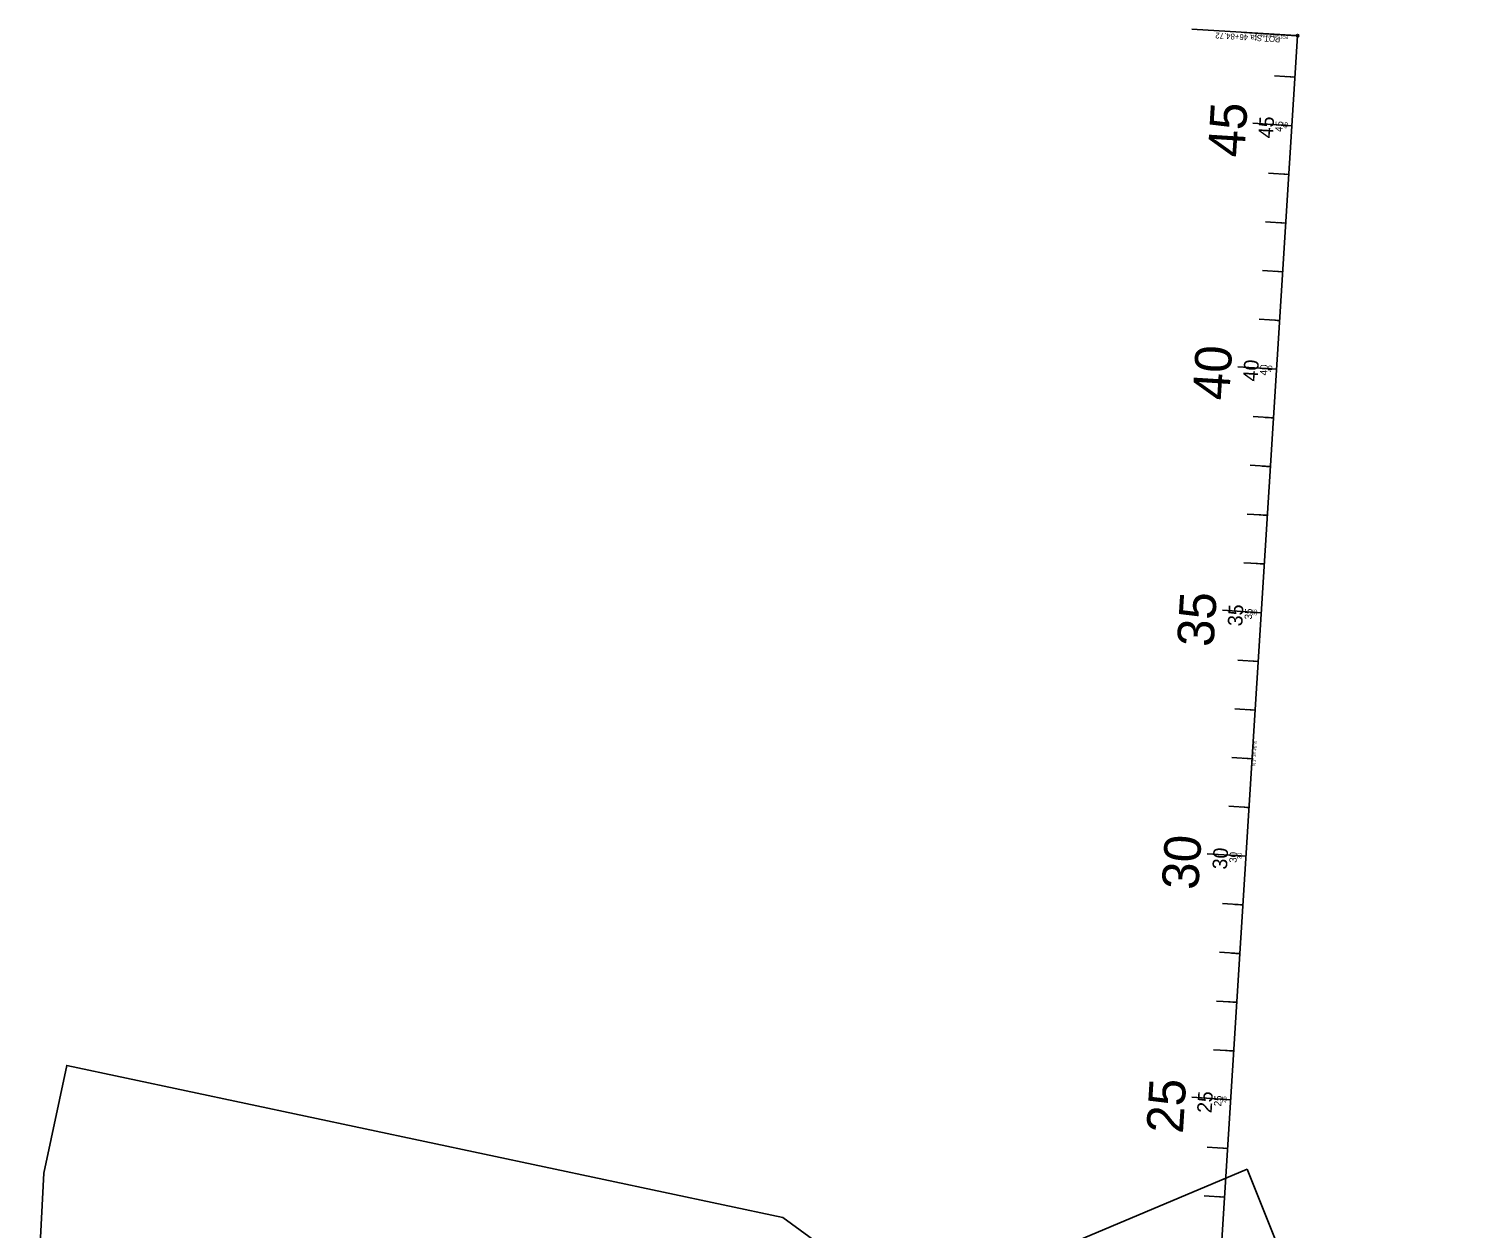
# Model space of a CAD drawing. Extents: x 2358865 to 2362945, y 393485 to 404880.
# Drawn here: x 2359965 to 2362945, y 402421 to 404880 of the extents above; entities that cross this region are included whole.
import ezdxf

# ---------------------------------------------------------------- set-up
doc = ezdxf.new("R2010")
doc.units = 0
for name, color, linetype in [('CL', 7, 'Continuous'), ('Level 21', 7, 'Continuous'), ('Level 25', 7, 'Continuous'), ('Level 28', 7, 'Continuous'), ('Level 30', 7, 'Continuous'), ('Level 33', 7, 'Continuous'), ('Level 39', 7, 'Continuous'), ('Level 41', 7, 'Continuous'), ('Level 63', 7, 'Continuous')]:
    doc.layers.add(name, color=color, linetype=linetype)

msp = doc.modelspace()

# ---------------------------------------------------------------- linework, layer by layer
at = {"layer": 'CL'}
msp.add_line((2362381, 401942.4), (2362564.8, 404866.6), dxfattribs=at)
at = {"layer": 'Level 25'}
for p, q in [((2362559.5, 404782), (2362554.5, 404782.3)), ((2362553.2, 404682.2), (2362545.2, 404682.7)), ((2362546.9, 404582.4), (2362541.9, 404582.7)), ((2362540.6, 404482.6), (2362535.7, 404482.9)), ((2362534.4, 404382.8), (2362529.4, 404383.1)), ((2362528.1, 404283), (2362523.1, 404283.3)), ((2362521.8, 404183.2), (2362513.8, 404183.7)), ((2362515.6, 404083.4), (2362510.6, 404083.7)), ((2362509.3, 403983.6), (2362504.3, 403983.9)), ((2362503, 403883.8), (2362498, 403884.1)), ((2362496.7, 403784), (2362491.8, 403784.3)), ((2362490.5, 403684.2), (2362482.5, 403684.7)), ((2362484.2, 403584.4), (2362479.2, 403584.7)), ((2362477.9, 403484.6), (2362472.9, 403484.9)), ((2362471.7, 403384.8), (2362466.7, 403385.1)), ((2362465.4, 403285), (2362460.4, 403285.3)), ((2362459.1, 403185.2), (2362451.1, 403185.7)), ((2362452.8, 403085.4), (2362447.8, 403085.7)), ((2362446.6, 402985.6), (2362441.6, 402985.9)), ((2362440.3, 402885.8), (2362435.3, 402886.1)), ((2362434, 402786), (2362429, 402786.3)), ((2362427.7, 402686.2), (2362419.8, 402686.7)), ((2362421.5, 402586.4), (2362416.5, 402586.7)), ((2362415.2, 402486.6), (2362410.2, 402486.9))]:
    msp.add_line(p, q, dxfattribs=at)
at = {"layer": 'Level 28'}
msp.add_line((2362563.5, 404866.7), (2362455.2, 404873.5), dxfattribs=at)
msp.add_circle((2362564.8, 404866.6), 1.25, dxfattribs=at)
at = {"layer": 'Level 30'}
for p, q in [((2362559.5, 404782), (2362551, 404782.6)), ((2362553.2, 404682.2), (2362537.2, 404683.2)), ((2362546.9, 404582.4), (2362538.4, 404583)), ((2362540.6, 404482.6), (2362532.2, 404483.2)), ((2362534.4, 404382.8), (2362525.9, 404383.4)), ((2362528.1, 404283), (2362519.6, 404283.6)), ((2362521.8, 404183.2), (2362505.9, 404184.2)), ((2362515.6, 404083.4), (2362507.1, 404083.9)), ((2362509.3, 403983.6), (2362500.8, 403984.1)), ((2362503, 403883.8), (2362494.5, 403884.3)), ((2362496.7, 403784), (2362488.3, 403784.5)), ((2362490.5, 403684.2), (2362474.5, 403685.2)), ((2362484.2, 403584.4), (2362475.7, 403584.9)), ((2362477.9, 403484.6), (2362469.4, 403485.1)), ((2362471.7, 403384.8), (2362463.2, 403385.3)), ((2362465.4, 403285), (2362456.9, 403285.5)), ((2362459.1, 403185.2), (2362443.1, 403186.2)), ((2362452.8, 403085.4), (2362444.4, 403085.9)), ((2362446.6, 402985.6), (2362438.1, 402986.1)), ((2362440.3, 402885.8), (2362431.8, 402886.3)), ((2362434, 402786), (2362425.5, 402786.5)), ((2362427.7, 402686.2), (2362411.8, 402687.2)), ((2362421.5, 402586.4), (2362413, 402586.9)), ((2362415.2, 402486.6), (2362406.7, 402487.1))]:
    msp.add_line(p, q, dxfattribs=at)
at = {"layer": 'Level 33'}
msp.add_line((2362562.1, 404866.8), (2362347.9, 404880.2), dxfattribs=at)
msp.add_circle((2362564.8, 404866.6), 2.7, dxfattribs=at)
at = {"layer": 'Level 39'}
for p, q in [((2362559.5, 404782), (2362542.5, 404783.1)), ((2362553.2, 404682.2), (2362521.3, 404684.2)), ((2362546.9, 404582.4), (2362530, 404583.5)), ((2362540.6, 404482.6), (2362523.7, 404483.7)), ((2362534.4, 404382.8), (2362517.4, 404383.9)), ((2362528.1, 404283), (2362511.1, 404284.1)), ((2362521.8, 404183.2), (2362489.9, 404185.2)), ((2362515.6, 404083.4), (2362498.6, 404084.5)), ((2362509.3, 403983.6), (2362492.3, 403984.7)), ((2362503, 403883.8), (2362486, 403884.9)), ((2362496.7, 403784), (2362479.8, 403785.1)), ((2362490.5, 403684.2), (2362458.5, 403686.2)), ((2362484.2, 403584.4), (2362467.2, 403585.5)), ((2362477.9, 403484.6), (2362461, 403485.7)), ((2362471.7, 403384.8), (2362454.7, 403385.9)), ((2362465.4, 403285), (2362448.4, 403286.1)), ((2362459.1, 403185.2), (2362427.2, 403187.2)), ((2362452.8, 403085.4), (2362435.9, 403086.4)), ((2362446.6, 402985.6), (2362429.6, 402986.6)), ((2362440.3, 402885.8), (2362423.3, 402886.8)), ((2362434, 402786), (2362417.1, 402787)), ((2362427.7, 402686.2), (2362395.8, 402688.2)), ((2362421.5, 402586.4), (2362404.5, 402587.4)), ((2362415.2, 402486.6), (2362398.2, 402487.6))]:
    msp.add_line(p, q, dxfattribs=at)
at = {"layer": 'Level 41'}
for p, q in [((2362559.5, 404782), (2362517.5, 404784.7)), ((2362553.2, 404682.2), (2362473.3, 404687.2)), ((2362546.9, 404582.4), (2362505, 404585.1)), ((2362540.6, 404482.6), (2362498.7, 404485.3)), ((2362534.4, 404382.8), (2362492.5, 404385.5)), ((2362528.1, 404283), (2362486.2, 404285.7)), ((2362521.8, 404183.2), (2362442, 404188.2)), ((2362515.6, 404083.4), (2362473.6, 404086)), ((2362509.3, 403983.6), (2362467.4, 403986.2)), ((2362503, 403883.8), (2362461.1, 403886.4)), ((2362496.7, 403784), (2362454.8, 403786.6)), ((2362490.5, 403684.2), (2362410.6, 403689.2)), ((2362484.2, 403584.4), (2362442.3, 403587)), ((2362477.9, 403484.6), (2362436, 403487.2)), ((2362471.7, 403384.8), (2362429.7, 403387.4)), ((2362465.4, 403285), (2362423.5, 403287.6)), ((2362459.1, 403185.2), (2362379.3, 403190.2)), ((2362452.8, 403085.4), (2362410.9, 403088)), ((2362446.6, 402985.6), (2362404.6, 402988.2)), ((2362440.3, 402885.8), (2362398.4, 402888.4)), ((2362434, 402786), (2362392.1, 402788.6)), ((2362427.7, 402686.2), (2362347.9, 402691.2)), ((2362421.5, 402586.4), (2362379.6, 402589)), ((2362415.2, 402486.6), (2362373.3, 402489.2))]:
    msp.add_line(p, q, dxfattribs=at)
at = {"layer": 'Level 63'}
for points in [[(2359964.7, 401954.9), (2361163.4, 401700.4), (2361426.4, 402053.5), (2361426.4, 402053.5), (2361515.9, 402173.8), (2361644.3, 402346.2), (2361509.4, 402444.8), (2360042.1, 402756.3), (2359995.2, 402535.3), (2359995.2, 402535.3)], [(2362461.5, 402543.9), (2361764.4, 402249.8), (2362269.7, 401052), (2362944.6, 401336.8)]]:
    msp.add_lwpolyline(points, close=True, dxfattribs=at)

# ---------------------------------------------------------------- texts
at = {"layer": 'Level 21'}
msp.add_text('N 3%%d 35\' 46" E', height=6, rotation=86.4038, dxfattribs=at).set_placement((2362478.2, 403369.9))
at = {"layer": 'Level 25'}
for s, p in [('45', (2362543.5, 404676.1)), ('40', (2362512.2, 404177.2)), ('35', (2362480.8, 403677.6)), ('30', (2362449.4, 403178.7)), ('25', (2362418.1, 402679.6))]:
    msp.add_text(s, height=8.75, rotation=86.4038, dxfattribs=at).set_placement(p)
at = {"layer": 'Level 28'}
msp.add_text('POT Sta 46+84.72', height=6, rotation=176.4038, dxfattribs=at).set_placement((2362545.9, 404865.8))
at = {"layer": 'Level 30'}
for s, p in [('45', (2362533.6, 404669)), ('40', (2362502.3, 404170.2)), ('35', (2362470.8, 403670)), ('30', (2362439.5, 403171.2)), ('25', (2362408.1, 402672.1))]:
    msp.add_text(s, height=15, rotation=86.4038, dxfattribs=at).set_placement(p)
at = {"layer": 'Level 33'}
msp.add_text('POT Sta 46+84.72', height=12, rotation=176.4038, dxfattribs=at).set_placement((2362529.6, 404864.8))
at = {"layer": 'Level 39'}
for s, p in [('45', (2362514.1, 404655.8)), ('40', (2362482.7, 404157.3)), ('35', (2362451.2, 403655.8)), ('30', (2362419.9, 403157.2)), ('25', (2362388.5, 402658))]:
    msp.add_text(s, height=30, rotation=86.4038, dxfattribs=at).set_placement(p)
at = {"layer": 'Level 41'}
for s, p in [('45', (2362455.3, 404616.1)), ('40', (2362424.1, 404118.2)), ('35', (2362392.3, 403612.9)), ('30', (2362361, 403115)), ('25', (2362329.6, 402615.6))]:
    msp.add_text(s, height=75, rotation=86.4038, dxfattribs=at).set_placement(p)

doc.saveas('drawing.dxf')
